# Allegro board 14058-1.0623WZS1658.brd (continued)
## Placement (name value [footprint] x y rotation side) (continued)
PR4413  4K32R2F-GP  [R402H16]  50.49 252.59 90 bottom
PR4414  31K6R2F-GP  [R402H16]  52.27 254.37 270 top
PR4415  51R2F-2-GP  [R402H16]  50.49 253.86 90 bottom
PR4416  4K99R2F-L-GP  [R402H16]  40.46 238.62 0 top
PR4417  5K9R2F-GP  [R402H16]  39.95 237.1 270 top
PR4418  24K9R2F-L-GP  [R402H16]  45.03 251.19 90 top
PR4419  4K99R2F-L-GP  [R402H16]  48.08 254.24 0 bottom
PR4420  5K9R2F-GP  [R402H16]  50.36 255.51 270 bottom
PR4421  10R2J-2-GP  [R402H14]  50.87 241.67 270 bottom
PR4422  10R2J-2-GP  [R402H14]  50.87 239.25 90 bottom
PR4423  80K6R2F-GP  [R402H16]  52.39 243.45 180 bottom
PR4424  22K1R2F-L-GP  [R402H16]  48.96 244.72 270 bottom
PR4425  174KR2F-GP  [R402H16]  52.65 244.46 270 top
PR4426  100KR2F-L1-GP  [R402H16]  54.3 245.22 0 top
PR4427  4K02R2F-GP  [R402H16]  50.87 243.06 90 bottom
PR4428  100KR2F-L1-GP  [R402H16]  49.22 241.67 0 bottom
PR4429  4K02R2F-GP  [R402H16]  50.87 240.52 90 bottom
PR4430  100KR2F-L1-GP  [R402H16]  49.22 239.64 0 bottom
PR4431  10R2J-2-GP  [R402H14]  29.15 242.05 0 top
PR4432  10R2J-2-GP  [R402H14]  31.82 240.91 180 top
PR4433  10R2J-2-GP  [R402H14]  38.55 239.13 180 top
PR4434  80K6R2F-GP  [R402H16]  53.16 242.3 0 top
PR4435  120KR2F-L-GP  [R402H16]  29.41 243.57 90 top
PR4436  120KR2F-L-GP  [R402H16]  34.87 239.25 270 top
PR4437  120KR2F-L-GP  [R402H16]  36.52 239.13 0 top
PR4438  21KR2F-GP  [R402H16]  34.99 245.99 0 bottom
PR4439  100KR2F-L1-GP  [R402H16]  32.2 247.64 0 top
PR4440  180KR2F-GP  [R402H16]  32.58 245.99 90 top
PR4441  4K02R2F-GP  [R402H16]  32.58 243.7 90 top
PR4442  4K02R2F-GP  [R402H16]  34.11 240.91 180 top
PR4443  4K02R2F-GP  [R402H16]  36.39 237.6 90 top
PR4444  100KR2F-L1-GP  [R402H16]  34.23 242.94 180 top
PR4445  100KR2F-L1-GP  [R402H16]  32.96 240.91 180 top
PR4446  100KR2F-L1-GP  [R402H16]  38.04 238.75 90 bottom
PR4447  100R2F-L1-GP-U  [R402H14]  39.06 253.48 90 top
PR4448  45D3R2F-L-GP  [R402H16]  39.06 251.19 90 top
PR4449  75R2F-2-GP  [R402H16]  39.06 252.34 90 top
PR4450  1KR2F-3-GP  [R402H16]  35.5 249.8 0 bottom
PR4451  47R2F-GP  [R402H16]  33.85 250.43 270 bottom
PR4452  4K02R2F-GP  [R402H16]  31.31 248.91 0 bottom
PR4453  560KR2F-GP  [R402H16]  34.36 248.91 0 bottom
PR4454  4K02R2F-GP  [R402H16]  52.65 247.76 90 bottom
PR4455  1KR2F-3-GP  [R402H16]  49.98 246.87 0 bottom
PR4456  560KR2F-GP  [R402H16]  48.84 246.87 0 bottom
PR4457  47R2F-GP  [R402H16]  50.11 249.03 180 bottom
PR4458  10KR2F-2-GP  [R402H16]  45.03 250.05 90 top
PR4459  10R2F-L-GP  [R402H14]  38.8 253.1 0 bottom
PR4460  49D9R2F-GP  [R402H16]  41.09 253.1 0 bottom
PR4461  10KR2F-2-GP  [R402H16]  46.68 238.87 270 bottom
PR4462  36K5R2F-GP  [R402H16]  44.27 238.11 180 bottom
PR4464  NTC-100K-12-GP-U  [NTC-402H22-U]  63.06 251.65 0 bottom
PR4465  NTC-100K-12-GP-U  [NTC-402H22-U]  75.89 241.41 90 top
PR4466  NTC-100K-12-GP-U  [NTC-402H22-U]  31.95 188.33 270 top
PR4467  0R0402-PAD-2-GP  [0R0402-PAD-1]  39.95 253.1 180 bottom
PR4468  0R2J-2-GP  [R402H16]  32.58 242.56 270 top
PR4473  15KR2F-GP  [R402H16]  46.68 237.73 270 bottom
PR4474  52K3R2F-L-GP  [R402H16]  41.6 238.49 0 top
PR4475  10KR2J-3-GP  [R402H16]  149.68 122.8 90 top
PR4476  2D2R5J-1-GP  [R805H24]  45.41 255.38 90 bottom
PR4477  2KR2F-3-GP  [R402H16]  32.58 244.84 90 top
PR4801  100R2F-L1-GP-U  [R402H14]  24.33 163.05 180 top
PR4802  0R0402-PAD-2-GP  [0R0402-PAD-1]  24.45 164.96 0 top
PR4803  0R0402-PAD-2-GP  [0R0402-PAD-1]  23.31 164.96 0 top
PR5268  0R0402-PAD-2-GP  [0R0402-PAD-1]  71.11 34.01 270 top
PR5270  316KR3F-2-GP  [R603H22]  71.7 35.55 0 bottom
PR5274  -  [0R0402-PAD]  70.43 35.29 0 bottom
PR5276  D01R3721F-GP-U  [R3720H40]  82.56 43.5 180 top
PR5277  0R0402-PAD-2-GP  [0R0402-PAD-1]  72.72 33.25 180 top
PR5279  100KR2J-1-GP  [R402H16]  72.74 42.43 0 top
PR5281  1D5R2F-GP  [R402H16]  78.43 36.31 90 top
PR5284  20R5F-1GP  [R805H24]  77.29 33.77 0 bottom
PR5285  0R0402-PAD-2-GP  [0R0402-PAD-1]  73.76 33.25 180 top
PR5286  49K9R2F-L-GP  [R402H16]  71.44 38.72 90 bottom
PR5288  3D3MR2J-GP  [R402H16]  74.24 42.91 270 top
PR5290  -  [0R0402-PAD]  69.41 42.66 0 bottom
PR5291  100KR2J-1-GP  [R402H16]  72.33 45.45 180 top
PR5301  -  [0R0805-PAD]  6.8 133.72 90 bottom
PR5302  10KR2F-2-GP  [R402H16]  17.34 110.73 90 bottom
PR5303  10KR2F-2-GP  [R402H16]  7.82 119.75 90 bottom
PR5304  -  [0R0805-PAD]  9.9 107.63 270 top
PR5305  10KR2F-2-GP  [R402H16]  7.82 117.46 90 bottom
PR5306  88K7R2F-GP  [R402H16]  7.94 114.41 270 bottom
PR5307  2D2R5J-1-GP  [R805H24]  16.71 128.26 0 bottom
PR5308  2D2R5J-1-GP  [R805H24]  15.94 114.92 180 bottom
PR5309  10KR2F-2-GP  [R402H16]  7.94 113.4 90 bottom
PR5467  102KR2F-GP  [R402H16]  69.92 40.75 180 bottom
PR5468  53K6R2F-GP  [R402H16]  67.76 40.25 270 top
PR5469  45K3R2F-L-GP  [R402H16]  68.15 41.74 0 top
PR5470  120KR2F-L-GP  [R402H16]  67.06 41.78 180 top
PR5471  -  [0R0805-PAD]  6.8 232.27 90 top
PR5472  -  [0R0805-PAD]  6.8 230.24 90 top
PR5473  -  [0R0805-PAD]  6.8 228.21 90 top
PR5474  -  [0R0805-PAD]  6.8 215 90 top
PR5475  -  [0R0805-PAD]  6.8 217.03 90 top
PR5476  -  [0R0805-PAD]  6.8 212.97 90 top
PR5477  -  [0R0805-PAD]  121.61 257.92 90 top
PR5478  -  [0R0805-PAD]  121.61 261.99 90 top
PR5479  -  [0R0805-PAD]  121.61 264.02 90 top
PR5480  -  [0R0805-PAD]  121.61 259.96 90 top
PR5481  -  [0R0805-PAD]  157.83 110.73 180 top
PR5482  -  [0R0805-PAD]  159.76 110.73 180 top
PR5518  10KR2F-2-GP  [R402H16]  15.18 110.1 180 bottom
PR5519  -  [0R0805-PAD]  21.91 81.9 90 top
PR5520  -  [0R0805-PAD]  21.91 83.93 90 top
PR5521  -  [0R0805-PAD]  26.49 67.75 90 top
PR5522  10KR2J-3-GP  [R402H16]  95.27 102.35 0 top
PR5523  10KR2J-3-GP  [R402H16]  77.03 77.08 90 top
PR5525  10KR2J-3-GP  [R402H16]  38.8 106.67 90 top
PR8302  2D2R5J-1-GP  [R805H24]  104.64 107.3 180 top
PR8303  20KR2F-L-GP  [R402H16]  99.61 108.83 270 top
PR8304  100KR2F-L1-GP  [R402H16]  104.46 97.65 270 top
PR8305  2KR2F-3-GP  [R402H16]  97.73 105.27 0 top
PR8306  0R0402-PAD-2-GP  [0R0402-PAD-1]  97.96 100.32 270 bottom
PR8308  33KR2F-GP  [R402H16]  100.5 108.65 180 bottom
PR8309  20KR2F-L-GP  [R402H16]  97.73 105.27 0 bottom
PR8311  10KR2F-2-GP  [R402H16]  97 103.69 270 top
PR8312  35K7R2F-GP  [R402H16]  106.7 99.91 0 top
PR8313  2D2R5J-1-GP  [R805H24]  105.61 96.13 0 bottom
PR8315  -  [0R0402-PAD]  105.35 96.13 180 top
PR8316  18KR2F-GP  [R402H16]  96.59 105.85 180 top
PR8317  0R0402-PAD-2-GP  [0R0402-PAD-1]  96.84 102.98 0 bottom
PR8318  51R2F-2-GP  [R402H16]  98.62 102.86 0 top
PR8319  -  [0R0402-PAD]  103.83 95.62 270 top
PR8320  0R2J-2-GP  [R402H16]  96.59 107.99 180 top
PR8323  5K9R3F-3-GP  [R603H22]  101.42 96 0 top
PR8324  0R0402-PAD-2-GP  [0R0402-PAD-1]  100.3 106.21 180 top
PR8325  -  [0R0402-PAD]  103.88 109.76 90 top
PR8326  82KR2F-1-GP  [R402H16]  96.34 101.28 0 top
PR8327  100KR2F-L1-GP  [R402H16]  103.83 96.63 90 top
PR8328  47KR2J-2-GP  [R402H16]  102.63 108.27 90 top
PR8329  100R2F-L1-GP-U  [R402H14]  95.7 102.98 180 bottom
PR8330  2D2R5J-1-GP  [R805H24]  101.67 95.16 0 bottom
PR8331  10KR2J-3-GP  [R402H16]  114.5 101.08 0 bottom
PR8333  100R2F-L1-GP-U  [R402H14]  96.21 100.95 180 bottom
PR8334  47KR2F-GP  [R402H16]  100.65 100.95 180 bottom
PR8335  1KR2J-1-GP  [R402H16]  100.4 106.29 90 bottom
PR8338  0R0402-PAD-2-GP  [0R0402-PAD-1]  39.19 105.07 0 top
PR8339  0R2J-2-GP  [R402H16]  38.07 105.07 0 top
PR8609  -  [0R0402-PAD]  46.93 86.6 90 top
PR8610  -  [0R0402-PAD]  39.69 111.49 90 top
PR8611  -  [0R0402-PAD]  39.69 110.35 90 top
PR8612  -  [0R0402-PAD]  46.93 88.63 90 top
PR8613  -  [0R0402-PAD]  46.93 89.65 90 top
PR8614  -  [0R0402-PAD]  46.93 90.66 90 top
PR8615  2D2R5J-1-GP  [R805H24]  38.07 97.65 180 top
PR8616  2D2R2F-GP  [R402H16]  43.5 110.6 0 bottom
PR8617  100KR2F-L1-GP  [R402H16]  37.25 101.28 90 top
PR8618  0R3J-0-U-GP  [R603H22]  45.03 109.46 180 top
PR8619  -  [0R0402-PAD]  46.93 85.46 90 top
PR8620  6K98R2F-GP  [R402H16]  38.68 103.49 90 top
PR8621  10KR2F-2-GP  [R402H16]  40.2 103.16 180 top
PR8622  -  [0R0402-PAD]  46.93 87.62 90 top
PR8623  10KR2J-3-GP  [R402H16]  37.53 107.68 90 top
PR8624  NTC-100K-12-GP-U  [NTC-402H22-U]  17.54 235.01 180 bottom
PR8625  3K3R2J-3-GP  [R402H16]  68.14 38.09 90 top
PR8626  3K3R2J-3-GP  [R402H16]  68.14 39.1 90 top
PSWD1  JOWLE-CON2-5-GP  [A2541WV0-1EX2PA-6T]  144.6 124.06 270 top
PT1  SE47U25VM-13-GP  [SE361414H241]  12.52 199.5 180 top
PT2  E820U2D5VM-6-GP  [ECAP-100D6D3H375]  43.12 219.19 270 top
PT3  E820U2D5VM-6-GP  [ECAP-100D6D3H375]  43 187.69 270 top
PT4  E820U2D5VM-6-GP  [ECAP-100D6D3H375]  43 195.57 270 top
PT5  E820U2D5VM-6-GP  [ECAP-100D6D3H375]  43 203.44 270 top
PT6  E820U2D5VM-6-GP  [ECAP-100D6D3H375]  43.12 211.31 270 top
PT7  SE47U25VM-13-GP  [SE361414H241]  12.52 218.3 180 top
PT8  SE47U25VM-13-GP  [SE361414H241]  12.52 227.7 0 top
PT9  SE47U25VM-13-GP  [SE361414H241]  84.14 256.83 90 top
PT11  E820U2D5VM-6-GP  [ECAP-100D6D3H375]  77.79 237.1 270 top
PT12  E820U2D5VM-6-GP  [ECAP-100D6D3H375]  81.6 230.11 270 top
PT13  E820U2D5VM-6-GP  [ECAP-100D6D3H375]  85.67 237.1 270 top
PT14  E820U2D5VM-6-GP  [ECAP-100D6D3H375]  89.48 230.11 270 top
PT15  SE47U25VM-13-GP  [SE361414H241]  115.64 256.65 0 top
PT16  SE47U25VM-13-GP  [SE361414H241]  27.76 148.45 90 top
PT17  E820U2D5VM-6-GP  [ECAP-100D6D3H375]  43.63 170.67 270 top
PT18  E820U2D5VM-6-GP  [ECAP-100D6D3H375]  43.63 162.8 270 top
PT20  E820U2D5VM-6-GP  [ECAP-100D6D3H375]  39.31 180.58 180 top
PT22  SE47U25VM-13-GP  [SE361414H241]  32.58 68.82 180 top
PT23  SE220U6D3VM-18-GP  [SE341619H241]  54.55 79.74 180 top
PT24  SE220U6D3VM-18-GP  [SE341619H241]  65.35 67.55 180 top
PT25  SE47U25VM-13-GP  [SE361414H241]  160.09 217.41 0 top
PT26  E820U2D5VM-6-GP  [ECAP-100D6D3H375]  128.09 220.46 270 top
PT27  E820U2D5VM-6-GP  [ECAP-100D6D3H375]  128.09 212.58 270 top
PT28  SE47U25VM-13-GP  [SE361414H241]  156.15 116.45 270 top
PT29  E820U2D5VM-6-GP  [ECAP-100D6D3H375]  158.13 103.2 180 top
PT30  E820U2D5VM-6-GP  [ECAP-100D6D3H375]  167.84 97.75 180 top
PT32  E820U2D5VM-6-GP  [ECAP-100D6D3H375]  109.04 119.75 270 top
PT34  E820U2D5VM-6-GP  [ECAP-100D6D3H375]  108.91 111.62 270 top
PT35  SE47U25VM-13-GP  [SE361414H241]  112.46 85.08 90 top
PU1  AON6520-GP  [PPAK-8P-5262H40]  110.56 97.4 180 top
PU2  AON6520-GP  [PPAK-8P-5262H40]  19.63 198.36 90 top
PU3  AON6520-GP  [PPAK-8P-5262H40]  19.63 198.36 270 bottom
PU4  NCP81151MNTBG-GP  [DFN8G2-G1309-UH40]  10.61 189.34 90 top
PU5  AON6510-GP  [PPAK-8P-5262H40]  21.41 189.47 270 top
PU6  AON6510-GP  [PPAK-8P-5262H40]  21.41 189.47 90 bottom
PU7  AON6520-GP  [PPAK-8P-5262H40]  19.63 214.87 90 top
PU8  AON6520-GP  [PPAK-8P-5262H40]  19.63 214.87 270 bottom
PU9  NCP81151MNTBG-GP  [DFN8G2-G1309-UH40]  10.61 208.14 90 top
PU10  AON6510-GP  [PPAK-8P-5262H40]  21.41 205.98 270 top
PU11  AON6510-GP  [PPAK-8P-5262H40]  21.41 205.98 90 bottom
PU12  AON6520-GP  [PPAK-8P-5262H40]  19.63 230.62 90 top
PU13  AON6520-GP  [PPAK-8P-5262H40]  19.63 230.62 270 bottom
PU14  NCP81151MNTBG-GP  [DFN8G2-G1309-UH40]  13.4 235.32 0 top
PU15  AON6510-GP  [PPAK-8P-5262H40]  21.41 221.73 270 top
PU16  AON6510-GP  [PPAK-8P-5262H40]  21.41 221.73 90 bottom
PU17  AON6520-GP  [PPAK-8P-5262H40]  76.14 258.05 180 bottom
PU18  AON6520-GP  [PPAK-8P-5262H40]  76.14 258.05 0 top
PU19  NCP81151MNTBG-GP  [DFN8G2-G1309-UH40]  67.25 261.1 0 top
PU20  AON6510-GP  [PPAK-8P-5262H40]  67 251.32 0 bottom
PU21  AON6510-GP  [PPAK-8P-5262H40]  67 251.32 180 top
PU22  AON6520-GP  [PPAK-8P-5262H40]  108.27 259.7 180 bottom
PU23  AON6520-GP  [PPAK-8P-5262H40]  108.27 259.7 0 top
PU24  NCP81151MNTBG-GP  [DFN8G2-G1309-UH40]  92.91 260.34 180 top
PU25  AON6510-GP  [PPAK-8P-5262H40]  99.26 258.05 0 bottom
PU26  AON6510-GP  [PPAK-8P-5262H40]  99.26 258.05 180 top
PU27  AON6520-GP  [PPAK-8P-5262H40]  25.72 155.43 180 top
PU28  NCP5230MNTWG-GP-U  [QFN16G3-G1D85-UH40]  25.72 136.64 0 top
PU29  AON6510-GP  [PPAK-8P-5262H40]  32.33 157.21 180 bottom
PU30  AON6510-GP  [PPAK-8P-5262H40]  32.33 157.21 0 top
PU31  AON7410-GP  [PPAK-8P-3232H36]  23.06 180.07 90 top
PU32  RT8237CZQW-2-GP  [DFN10G3-G265175H32]  20.64 168.01 180 top
PU33  AON7506-GP  [PPAK-8P-3232H36]  24.58 175.63 270 top
PU34  AON7410-GP  [PPAK-8P-3232H36]  38.35 81.77 90 top
PU35  RT8243AZQW-GP  [QFN20-G1D75H32]  29.28 75.68 270 bottom
PU36  AON6520-GP  [PPAK-8P-5262H40]  42.74 65.01 90 top
PU37  AON7506-GP  [PPAK-8P-3232H36]  39.87 77.33 270 top
PU38  AON6510-GP  [PPAK-8P-5262H40]  44.52 71.61 270 top
PU39  AON6520-GP  [PPAK-8P-5262H40]  150.69 218.81 270 top
PU40  RT8207PGQW-GP  [QFN20-G1D75H32]  168.63 215.62 90 bottom
PU41  AON6510-GP  [PPAK-8P-5262H40]  148.91 212.2 270 bottom
PU42  AON6510-GP  [PPAK-8P-5262H40]  148.91 212.2 90 top
PU43  AON6520-GP  [PPAK-8P-5262H40]  164.15 120.64 0 top
PU44  RT8237CZQW-2-GP  [DFN10G3-G265175H32]  154.63 124.45 270 bottom
PU45  AON6510-GP  [PPAK-8P-5262H40]  170.76 118.86 180 top
PU46  AON6510-GP  [PPAK-8P-5262H40]  170.76 118.86 0 bottom
PU4401  NCP81203MNTXG-SI2-GP  [LFQFN52J6-G4D8H40]  42.11 245.48 180 bottom
PU5202  AON6510-GP  [PPAK-8P-5262H40]  119.2 99.05 0 top
PU5203  AON6520-GP  [PPAK-8P-5262H40]  110.56 97.4 0 bottom
PU5204  AON6510-GP  [PPAK-8P-5262H40]  119.2 99.05 180 bottom
PU5301  RT8289GSP-GP  [SOIC8-G2D3H70]  11.88 116.95 180 bottom
PU5302  APL5930KAI-TRG-1-GP  [SOIC8-G3530H63]  105.73 129.65 270 top
PU8602  APW8713QBI-GP  [QFN23G4-G2PH34]  44.01 104.13 90 top
PWRCN1  ACES-CON10-30-GP  [51530-01041-W01]  33.75 18.17 270 top
Q1  DMN5L06K-7-GP  [SOT23DGS2D4H48]  150.31 95.49 0 bottom
Q2  MMBT3904-5-GP  [SOT23CBE2D4H46]  151.38 101.48 180 top
Q3  2N7002H-GP  [SOT23DGS2D4H44]  154.12 95.49 180 bottom
Q4  DMN5L06K-7-GP  [SOT23DGS2D4H48]  150.31 95.49 180 top
Q5  MMBT3906-4-GP  [SOT23CBE2D4H44]  163.47 55.74 270 top
Q6  2N7002EDW-2-GP  [SOT-363H44]  122.85 59.64 180 bottom
Q7  2N7002A-7-GP  [SOT23DGS2D4H48]  185.36 57.52 0 top
Q8  2N7002H-GP  [SOT23DGS2D4H44]  110.86 58.03 0 bottom
Q10  2N7002KDW-GP  [SOT-363H44]  94.94 60.31 180 top
Q12  2N7002A-7-GP  [SOT23DGS2D4H48]  184.22 32.37 180 top
Q13  MMBT3904DW-GP  [SOT-363H44]  184.35 39.53 180 top
Q14  2N7002-11-GP  [SOT23DGS2D4H44]  181.93 72.38 270 top
Q15  AZ5125-02S-R7G-GP  [SOT23-2D4-312H46]  185.11 80.38 0 top
Q16  AZ5125-02S-R7G-GP  [SOT23-2D4-312H46]  182.06 76.19 90 top
Q17  AZ5125-02S-R7G-GP  [SOT23-2D4-312H46]  105.1 36.82 270 top
Q18  MMBT3904-4-GP  [SOT23CBE2D4H44]  178.25 73.9 0 top
Q23  MMBT3904DW-GP  [SOT-363H44]  52.14 43.29 180 top
Q24  2N7002A-7-GP  [SOT23DGS2D4H48]  51.76 28.31 90 bottom
Q26  MMBT3904-4-GP  [SOT23CBE2D4H44]  51.76 28.31 270 top
Q29  AO4468L-GP  [SOIC8H69]  81.86 57.77 270 bottom
Q30  2N7002A-7-GP  [SOT23DGS2D4H48]  79.14 56.07 0 top
Q31  2N7002A-7-GP  [SOT23DGS2D4H48]  77.64 62.47 270 top
Q53  2N7002A-7-GP  [SOT23DGS2D4H48]  96.51 112.76 90 top
Q54  AO3413L-GP  [SOT23DGS2D8H50]  96.59 119.87 0 top
Q56  AO3413L-GP  [SOT23DGS2D8H50]  141.8 227.82 0 bottom
Q57  2N7002K-2-GP  [SOT23DGS2D4H44]  125.57 254.08 270 top
Q58  2N7002A-7-GP  [SOT23DGS2D4H48]  147.95 236.44 270 bottom
Q59  MMBT3906-4-GP  [SOT23CBE2D4H44]  94.18 88.38 90 top
Q60  MMBT3904-4-GP  [SOT23CBE2D4H44]  147.95 240.05 270 bottom
Q61  MMBT3904-4-GP  [SOT23CBE2D4H44]  46.04 6.84 90 top
Q62  MMBT3904-4-GP  [SOT23CBE2D4H44]  49.73 6.92 180 top
Q63  MMBT3904-4-GP  [SOT23CBE2D4H44]  47.06 10.65 90 top
Q64  2N7002A-7-GP  [SOT23DGS2D4H48]  36.85 7.4 0 top
Q65  2N7002A-7-GP  [SOT23DGS2D4H48]  42.23 12.18 90 top
Q76  MMBT3904-4-GP  [SOT23CBE2D4H44]  170 206.62 270 bottom
Q103  2N7002A-7-GP  [SOT23DGS2D4H48]  28.62 54.19 270 top
Q1227  2N7002H-GP  [SOT23DGS2D4H44]  8.6 162.62 90 top
Q1228  2N7002KDW-GP  [SOT-363H44]  110.43 240.91 180 top
Q1233  2N7002EDW-2-GP  [SOT-363H44]  37.79 154.16 180 top
Q1234  AO3404AL-GP  [SOT23DGS2D8H50]  34.87 147.43 180 top
Q1249  2N7002A-7-GP  [SOT23DGS2D4H48]  169.87 52.95 0 bottom
Q1259  AO4286-GP  [SOIC8H69]  14.8 7.99 90 bottom
Q1260  MMBT3904-4-GP  [SOT23CBE2D4H44]  6.04 17.26 90 bottom
Q1261  2N7002A-7-GP  [SOT23DGS2D4H48]  18.74 38.85 90 bottom
Q1262  2N7002A-7-GP  [SOT23DGS2D4H48]  18.36 34.28 90 bottom
Q1263  MMBT3904-4-GP  [SOT23CBE2D4H44]  16.07 30.59 270 bottom
Q1264  AO3413L-GP  [SOT23DGS2D8H50]  51.89 24.24 0 top
Q1265  MMBT3904-4-GP  [SOT23CBE2D4H44]  55.95 19.42 0 bottom
Q1266  MMBT3904-4-GP  [SOT23CBE2D4H44]  55.97 19.47 180 top
Q1267  MMBT3904-4-GP  [SOT23CBE2D4H44]  57.35 14.34 90 top
Q6701  2N7002KDW-GP  [SOT-363H44]  26.49 110.35 0 top
Q6704  MMBT3904-4-GP  [SOT23CBE2D4H44]  109.8 83.43 270 bottom
Q7903  2N7002-7F-GP  [SOT23DGS2D4H44]  111.55 44.11 90 top
Q9501  2N7002KDW-GP  [SOT-363H44]  51 20.69 90 top
Q9502  2N7002KDW-GP  [SOT-363H44]  51 17.64 270 top
Q9503  2N7002KDW-GP  [SOT-363H44]  57.6 14.21 180 bottom
Q9601  AO3418L-GP  [SOT23DGS2D8H50]  38.04 39.99 180 bottom
Q9602  LMBT3906LT1G-1-GP  [SOT23CBE2D4H44]  43.76 40.75 270 bottom
Q9614  2N7002KDW-GP  [SOT-363H44]  28.01 27.8 0 bottom
Q9619  AO3418L-GP  [SOT23DGS2D8H50]  33.6 27.8 90 bottom
Q9620  2N7002KDW-GP  [SOT-363H44]  181.3 28.82 270 top
Q9624  AO3418L-GP  [SOT23DGS2D8H50]  16.71 173.6 270 top
Q9626  2N7002A-7-GP  [SOT23DGS2D4H48]  180.54 32.37 0 top
Q9628  MMBT3904DW-GP  [SOT-363H44]  19.12 44.18 180 bottom
Q9629  MMBT3904DW-GP  [SOT-363H44]  26.23 48.63 270 bottom
Q9630  2N7002K-2-GP  [SOT23DGS2D4H44]  105.73 90.79 180 top
Q9631  MMBT3904-4-GP  [SOT23CBE2D4H44]  94.18 88.38 270 bottom
Q9632  2N7002EDW-2-GP  [SOT-363H44]  90.21 130.31 90 top
Q9633  2N7002EDW-2-GP  [SOT-363H44]  96.34 130.54 90 top
Q9634  MMBT3904-4-GP  [SOT23CBE2D4H44]  82.24 48.25 90 bottom
Q9635  MMBT3904-4-GP  [SOT23CBE2D4H44]  93.16 57.52 90 bottom
Q9646  2N7002KDW-GP  [SOT-363H44]  41.47 8.24 180 top
Q9648  AO3413L-GP  [SOT23DGS2D8H50]  28.26 56.37 90 bottom
Q9650  2N7002A-7-GP  [SOT23DGS2D4H48]  32.07 54.6 180 bottom
R1  -  [0R0402-PAD]  102.05 192.9 270 bottom
R2  -  [0R0402-PAD]  102.05 194.04 270 bottom
R3  2R2F-GP  [R402H16]  109.42 224.9 270 bottom
R4  2R2F-GP  [R402H16]  109.42 226.05 270 bottom
R5  24D9R2F-L-GP  [R402H16]  105.1 225.67 90 bottom
R6  -  [0R0402-PAD]  82.49 144.39 0 bottom
R7  -  [0R0402-PAD]  81.35 144.39 0 bottom
R8  51R2F-2-GP  [R402H16]  57.73 139.56 270 top
R9  -  [0R0402-PAD]  83.8 143.75 180 top
R10  1KR2J-1-GP  [R402H16]  52.14 134.73 180 top
R11  -  [0R0402-PAD]  82.66 143.75 180 top
R12  51R2F-2-GP  [R402H16]  37.38 231.25 270 top
R13  -  [0R0402-PAD]  84.78 145.15 0 bottom
R14  51R2F-2-GP  [R402H16]  36.65 143.88 90 top
R15  -  [0R0402-PAD]  83.64 145.15 0 bottom
R16  56D2R2F-GP  [R402H16]  37.25 234.68 270 top
R17  45D3R2F-L-GP  [R402H16]  41.34 234.68 270 top
R18  100R2F-L1-GP-U  [R402H14]  41.34 231.25 270 top
R19  1MR2J-1-GP  [R402H16]  21.28 39.23 0 bottom
R20  10KR2J-3-GP  [R402H16]  109.42 232.14 180 top
R22  -  [0R0402-PAD]  37.25 235.83 270 top
R23  220R2F-GP  [R402H16]  37.25 233.54 270 top
R24  10KR2J-3-GP  [R402H16]  107.51 229.6 90 bottom
R25  0R2J-2-GP  [R402H16]  41.34 233.54 90 top
R27  -  [0R0402-PAD]  41.34 235.83 270 top
R28  0R2J-2-GP  [R402H16]  41.34 230.11 90 top
R30  -  [0R0402-PAD]  41.34 232.4 270 top
R31  0R2J-2-GP  [R402H16]  109.26 237.22 270 top
R32  51R2F-2-GP  [R402H16]  42.49 121.27 270 top
R33  6K04R2F-GP  [R402H16]  60.64 139.11 180 top
R35  2K8R2F-GP  [R402H16]  61.65 139.11 180 top
R37  -  [0R0402-PAD]  58.86 144.83 180 top
R38  -  [0R0402-PAD]  38.8 140.96 90 top
R39  0R0402-PAD-2-GP  [0R0402-PAD-1]  39.43 144.07 0 top
R40  0R0402-PAD-2-GP  [0R0402-PAD-1]  38.41 144.07 0 top
R41  0R2J-2-GP  [R402H16]  59.87 144.83 0 top
R42  10KR2J-3-GP  [R402H16]  18.48 31.23 0 bottom
R43  0R0402-PAD-2-GP  [0R0402-PAD-1]  32.92 116.83 270 top
R44  0R0402-PAD-2-GP  [0R0402-PAD-1]  61.03 145.53 0 top
R45  49D9R2F-GP  [R402H16]  70.05 179.44 0 top
R46  1KR2J-1-GP  [R402H16]  41.47 133.34 270 top
R47  1KR2J-1-GP  [R402H16]  41.47 132.19 270 top
R48  1KR2J-1-GP  [R402H16]  41.47 131.05 270 top
R49  1KR2J-1-GP  [R402H16]  51.63 131.69 90 top
R50  1KR2J-1-GP  [R402H16]  41.73 128.89 270 top
R51  1KR2J-1-GP  [R402H16]  41.47 146.8 270 top
R52  1KR2J-1-GP  [R402H16]  42.11 127.24 0 top
R53  1KR2J-1-GP  [R402H16]  41.47 145.78 270 top
R54  1KR2J-1-GP  [R402H16]  41.6 137.65 270 top
R55  1KR2J-1-GP  [R402H16]  37.03 157.72 90 top
R56  1KR2J-1-GP  [R402H16]  37.46 133.34 180 top
R57  1KR2J-1-GP  [R402H16]  36.31 133.34 180 top
R58  1KR2J-1-GP  [R402H16]  41.6 139.56 270 top
R59  1KR2J-1-GP  [R402H16]  39.57 146.04 0 top
R60  1KR2J-1-GP  [R402H16]  37.53 128.64 90 top
R61  1KR2J-1-GP  [R402H16]  37.53 127.49 90 top
R62  1KR2J-1-GP  [R402H16]  44.77 152.77 270 top
R63  24D9R2F-L-GP  [R402H16]  71.6 179.69 270 top
R64  -  [0R0402-PAD]  79.7 179.95 90 top
R65  0R2J-2-GP  [R402H16]  79.7 178.47 270 top
R66  20R2J-3-GP  [R402H16]  139.87 61.3 0 top
R68  0R3J-L1-GP  [R603H22]  37.28 145.91 180 top
R71  24D9R2F-L-GP  [R402H16]  71.65 178.57 90 top
R72  20R2F-GP  [R402H16]  147 61.33 180 top
R73  10KR2J-3-GP  [R402H16]  168.73 136.77 270 bottom
R74  10KR2J-3-GP  [R402H16]  145.74 136 0 bottom
R75  10KR2J-3-GP  [R402H16]  148.79 136 0 bottom
R76  1KR2F-3-GP  [R402H16]  143.93 194.97 90 bottom
R77  -  [0R0402-PAD]  143.45 197.6 0 bottom
R78  1KR2F-3-GP  [R402H16]  143.88 196.07 270 bottom
R79  2R2F-GP  [R402H16]  144.85 199.25 90 bottom
R80  24D9R2F-L-GP  [R402H16]  144.34 200.77 180 bottom
R81  0R0402-PAD-2-GP  [0R0402-PAD-1]  154.37 188.84 90 bottom
R82  1KR2F-3-GP  [R402H16]  154.12 156.07 0 bottom
R83  -  [0R0402-PAD]  153.61 157.59 270 bottom
R84  1KR2F-3-GP  [R402H16]  153.1 156.07 180 bottom
R85  10KR2J-3-GP  [R402H16]  160.72 136.13 180 bottom
R86  10KR2J-3-GP  [R402H16]  160.72 138.16 0 bottom
R87  1KR2F-3-GP  [R402H16]  160.34 193.79 270 bottom
R88  -  [0R0402-PAD]  159.84 195.31 0 bottom
R89  1KR2F-3-GP  [R402H16]  160.85 195.31 0 bottom
R90  2R2F-GP  [R402H16]  159.84 199 180 bottom
R91  24D9R2F-L-GP  [R402H16]  162.38 199 270 bottom
R92  0R0402-PAD-2-GP  [0R0402-PAD-1]  168.85 189.09 270 bottom
R93  1KR2F-3-GP  [R402H16]  169.11 159.63 90 bottom
R94  -  [0R0402-PAD]  169.11 158.48 270 bottom
R95  1KR2F-3-GP  [R402H16]  168.22 156.83 180 bottom
R96  10KR2J-3-GP  [R402H16]  164.03 78.09 0 top
R99  1KR2J-1-GP  [R402H16]  136.47 81.39 180 bottom
R100  1KR2J-1-GP  [R402H16]  134.88 94.33 180 top
R103  10KR2J-3-GP  [R402H16]  162.12 79.36 90 top
R104  499R2F-2-GP  [R402H16]  150.18 90.66 90 bottom
R105  499R2F-2-GP  [R402H16]  155.26 92.82 90 bottom
R106  33R2J-2-GP  [R402H16]  145.95 61.31 180 top
R107  33R2J-2-GP  [R402H16]  153.1 67.3 0 bottom
R108  33R2J-2-GP  [R402H16]  155.69 69.73 90 bottom
R109  33R2J-2-GP  [R402H16]  151.96 67.3 0 bottom
R111  33R2J-2-GP  [R402H16]  154.25 67.3 0 bottom
R113  33R2J-2-GP  [R402H16]  144.9 61.3 180 top
R115  -  [0R0402-PAD]  162.63 74.33 90 top
R116  10KR2J-3-GP  [R402H16]  165.17 73.77 180 top
R117  8K2R2J-3-GP  [R402H16]  153.66 102.25 180 top
R118  8K2R2J-3-GP  [R402H16]  148.15 100.19 90 top
R119  4K7R2J-2-GP  [R402H16]  165.93 72.12 90 top
R120  3KR2J-2-GP  [R402H16]  159.58 56.88 0 top
R122  10KR2J-3-GP  [R402H16]  138.63 67.17 0 bottom
R123  10KR2J-3-GP  [R402H16]  166.82 73.65 270 top
R124  1KR2J-1-GP  [R402H16]  151.83 98.03 90 bottom
R126  0R2J-2-GP  [R402H16]  156.03 78.22 0 bottom
R127  1KR2J-1-GP  [R402H16]  160.09 77.96 180 bottom
R128  2K2R2J-2-GP  [R402H16]  151.82 58.6 180 top
R131  0R0402-PAD-2-GP  [0R0402-PAD-1]  146.74 58.41 0 top
R132  51R2F-2-GP  [R402H16]  145.69 58.41 0 top
R133  1KR2J-1-GP  [R402H16]  151.83 98.03 270 top
R134  10KR2J-3-GP  [R402H16]  8.07 19.87 270 bottom
R135  4K7R2J-2-GP  [R402H16]  10.23 20.05 90 top
R137  1K5R2J-3-GP  [R402H16]  172.41 77.58 270 bottom
R138  20KR2F-L-GP  [R402H16]  147.26 121.4 180 top
R139  0R2J-2-GP  [R402H16]  158.57 56.88 180 top
R140  0R2J-2-GP  [R402H16]  152.09 121.27 0 top
R141  4K7R2J-2-GP  [R402H16]  147.26 125.46 0 top
R142  -  [0R0402-PAD]  157.42 57.39 0 top
R143  1KR2J-1-GP  [R402H16]  5.63 19.44 90 top
R145  33R2J-2-GP  [R402H16]  172.41 78.73 270 bottom
R146  20KR2F-L-GP  [R402H16]  148.91 120.89 180 top
R147  4K7R2J-2-GP  [R402H16]  150.95 120.89 0 top
R150  0R0402-PAD-2-GP  [0R0402-PAD-1]  134.69 123.3 180 top
R151  10KR2J-3-GP  [R402H16]  132.78 122.54 180 top
R152  4K7R2J-2-GP  [R402H16]  38.42 146.04 0 top
R153  1KR2J-1-GP  [R402H16]  162.65 58.15 270 top
R154  1KR2J-1-GP  [R402H16]  152.27 60.06 270 top
R155  -  [0R0402-PAD]  152.96 58.6 180 top
R156  10KR2J-3-GP  [R402H16]  157.64 77.37 90 top
R157  10KR2J-3-GP  [R402H16]  163.77 84.57 90 top
R158  10KR2J-3-GP  [R402H16]  144.28 91.88 90 bottom
R159  2K7R2F-GP  [R402H16]  133.42 63.23 180 top
R160  10KR2J-3-GP  [R402H16]  164.03 83.04 90 top
R161  10KR2J-3-GP  [R402H16]  164.15 80.76 90 top
R162  10KR2J-3-GP  [R402H16]  161.87 81.39 180 top
R163  -  [0R0402-PAD]  158.67 78.42 270 top
R164  -  [0R0402-PAD]  163.77 85.84 270 top
R165  10KR2J-3-GP  [R402H16]  157.55 86.47 270 bottom
R166  -  [0R0402-PAD]  144.18 93 270 bottom
R168  10KR2J-3-GP  [R402H16]  144.18 97.32 90 bottom
R169  10KR2J-3-GP  [R402H16]  160.22 84.66 270 top
R170  10KR2J-3-GP  [R402H16]  160.22 85.8 270 top
R172  10KR2J-3-GP  [R402H16]  157.55 87.62 270 bottom
R173  10KR2J-3-GP  [R402H16]  160.22 86.94 270 top
R174  10KR2J-3-GP  [R402H16]  157.55 88.76 270 bottom
R175  10KR2J-3-GP  [R402H16]  157.55 89.9 270 bottom
R176  10KR2J-3-GP  [R402H16]  157.49 85.14 90 top
R177  10KR2J-3-GP  [R402H16]  157.49 86.18 90 top
R178  1MR2J-1-GP  [R402H16]  124.1 69.15 0 top
R179  0R0402-PAD-2-GP  [0R0402-PAD-1]  161.87 69.96 270 top
R180  10MR3F-GP  [R603H22]  164.53 69.84 180 top
R181  100R2F-L1-GP-U  [R402H14]  125.67 74.31 0 top
R188  113R2F-GP  [R402H16]  143.83 67.04 180 bottom
R189  1KR2J-1-GP  [R402H16]  143.2 65.14 180 bottom
R190  1KR2J-1-GP  [R402H16]  144 71.87 90 bottom
R191  -  [0R0402-PAD]  143.02 94.5 180 top
R192  10KR2J-3-GP  [R402H16]  87.83 121.37 270 bottom
R193  200R2F-L-GP  [R402H16]  75.13 125.08 90 top
R194  80D6R2F-L-GP  [R402H16]  60.65 111.62 90 top
R195  162R2F-GP  [R402H16]  58.74 110.48 270 top
R196  10KR2J-3-GP  [R402H16]  157.68 74.79 90 bottom
R197  10KR2J-3-GP  [R402H16]  157.17 73.65 90 bottom
R198  33R2J-2-GP  [R402H16]  162.5 76.57 90 top
R199  10KR2J-3-GP  [R402H16]  130.5 101.21 90 top
R200  -  [0R0402-PAD]  159.2 73.65 270 bottom
R203  10KR2J-3-GP  [R402H16]  164.79 79.62 90 top
R205  4K7R2J-2-GP  [R402H16]  157.55 89.9 90 top
R217  4K7R2J-2-GP  [R402H16]  161.49 82.92 270 top
R218  4K7R2J-2-GP  [R402H16]  157.05 82.93 180 top
R219  10KR2F-2-GP  [R402H16]  99.13 98.03 90 top
R221  4K7R2J-2-GP  [R402H16]  148.28 92.06 180 bottom
R222  4K7R2J-2-GP  [R402H16]  147.52 94.22 90 bottom
R223  20KR2J-L2-GP  [R402H16]  147.52 95.36 270 bottom
R224  20KR2J-L2-GP  [R402H16]  148.28 90.54 90 bottom
R226  1KR2J-1-GP  [R402H16]  167.2 61.2 0 top
R227  20KR2J-L2-GP  [R402H16]  151.07 92.32 0 bottom
R228  20KR2J-L2-GP  [R402H16]  166.06 61.2 180 top
R229  2K2R2J-2-GP  [R402H16]  159.84 58.41 90 top
R231  10KR2F-2-GP  [R402H16]  99.13 96 90 top
R234  49K9R2F-L-GP  [R402H16]  99.13 96 90 bottom
R235  243R2F-2-GP  [R402H16]  91.28 81.82 90 top
R236  20KR2J-L2-GP  [R402H16]  157.68 80.76 270 bottom
R237  10KR2F-2-GP  [R402H16]  99.13 97.01 90 bottom
R238  10KR2F-2-GP  [R402H16]  99.13 97.01 90 top
R239  4K7R2J-2-GP  [R402H16]  157.55 83.55 90 bottom
R240  10KR2F-2-GP  [R402H16]  99.13 94.98 90 bottom
R241  80D6R2F-L-GP  [R402H16]  77.18 91.3 270 top
R243  10KR2F-2-GP  [R402H16]  99.13 94.98 90 top
R244  162R2F-GP  [R402H16]  77.54 88.84 0 top
R245  80D6R2F-L-GP  [R402H16]  77.18 90.28 270 top
R246  0R2J-2-GP  [R402H16]  139.95 70.39 180 bottom
R247  0R2J-2-GP  [R402H16]  142 72.6 270 bottom
R249  10KR2J-3-GP  [R402H16]  114.24 67.55 180 top
R250  17K8R2F-GP  [R402H16]  92.27 55.74 270 top
R251  1KR2J-1-GP  [R402H16]  111.83 61.58 180 bottom
R252  10KR2F-2-GP  [R402H16]  94.43 53.45 90 top
R253  2K2R2J-2-GP  [R402H16]  99.64 62.85 90 top
R254  2K2R2J-2-GP  [R402H16]  124.02 48.5 270 top
R255  6K49R2F-1-GP  [R402H16]  99.92 52.18 270 top
R256  -  [0R0402-PAD]  110.69 61.58 0 bottom
R257  10KR2J-3-GP  [R402H16]  113.1 48.4 0 bottom
R258  4K99R2F-L-GP  [R402H16]  90.8 88.45 180 top
R259  10KR2F-2-GP  [R402H16]  97.05 52.97 180 top
R260  10KR2F-2-GP  [R402H16]  91.26 52.31 90 top
R262  10KR2J-3-GP  [R402H16]  121.48 47.1 270 top
R263  10KR2J-3-GP  [R402H16]  117.54 60.26 180 bottom
R264  10KR2J-3-GP  [R402H16]  115.26 67.55 180 top
R265  10KR2J-3-GP  [R402H16]  95.95 63.74 270 top
R266  5K1R2F-2-GP  [R402H16]  101.29 51.8 90 bottom
R267  10KR2J-3-GP  [R402H16]  114.12 48.4 180 bottom
R268  10KR2J-3-GP  [R402H16]  115.28 48.39 180 bottom
R269  10KR2J-3-GP  [R402H16]  116.53 48.4 180 bottom
R270  10KR2J-3-GP  [R402H16]  111.19 68.95 180 top
R272  10KR2F-2-GP  [R402H16]  103.83 52.31 0 bottom
R277  10KR2J-3-GP  [R402H16]  99.64 62.72 270 bottom
R279  10KR2J-3-GP  [R402H16]  108.27 71.36 90 top
R280  10KR2F-2-GP  [R402H16]  108.27 70.34 270 top
R283  10KR2J-3-GP  [R402H16]  104.59 68.69 180 top
R284  1KR2J-1-GP  [R402H16]  124.02 49.77 90 top
R285  1KR2J-1-GP  [R402H16]  122.69 58.63 90 top
R286  1KR2J-1-GP  [R402H16]  99.92 53.2 270 top
R287  4K7R2F-GP  [R402H16]  125.35 60.69 270 top
R288  100KR2J-1-GP  [R402H16]  119.55 58.1 270 bottom
R290  10KR2F-2-GP  [R402H16]  123.39 55.23 270 bottom
R291  -  [0R0402-PAD]  99.38 56.5 270 top
R292  0R0402-PAD-2-GP  [0R0402-PAD-1]  122.9 56.77 180 bottom
R293  20KR2J-L2-GP  [R402H16]  119.88 55.76 180 bottom
R294  33R2J-2-GP  [R402H16]  115.84 58.25 90 bottom
R295  0R0402-PAD-2-GP  [0R0402-PAD-1]  99.38 57.52 270 top
R296  10KR2J-3-GP  [R402H16]  119.83 60.57 180 bottom
R297  0R0402-PAD-2-GP  [0R0402-PAD-1]  99.38 58.53 270 top
R298  33R2J-2-GP  [R402H16]  122.62 63.23 180 top
R299  0R0402-PAD-2-GP  [0R0402-PAD-1]  123.77 63.23 180 top
R300  100R2F-L1-GP-U  [R402H14]  99.64 65.01 270 top
R301  0R0402-PAD-2-GP  [0R0402-PAD-1]  119.7 63.36 0 bottom
R302  0R0402-PAD-2-GP  [0R0402-PAD-1]  99.64 66.03 270 top
R303  1KR2J-1-GP  [R402H16]  99.64 68.06 270 top
R304  0R3J-0-U-GP  [R603H22]  125.11 55.87 180 top
R305  -  [0R0603-PAD]  92.93 65.39 90 top
R306  0R0402-PAD-2-GP  [0R0402-PAD-1]  98.88 69.96 270 top
R307  0R0402-PAD-2-GP  [0R0402-PAD-1]  98.88 70.98 270 top
R308  10KR2F-2-GP  [R402H16]  94.05 70.85 270 top
R309  10KR2F-2-GP  [R402H16]  93.16 69.2 270 top
R310  10KR2F-2-GP  [R402H16]  92.68 67.6 270 top
R311  10KR2F-2-GP  [R402H16]  102.76 64.5 180 bottom
R312  10KR2F-2-GP  [R402H16]  102.18 67.17 270 bottom
R313  10KR2F-2-GP  [R402H16]  102.18 68.31 270 bottom
R314  10KR2J-3-GP  [R402H16]  123.13 57.52 90 top
R316  10KR2J-3-GP  [R402H16]  119.53 50.35 270 bottom
R317  10KR2J-3-GP  [R402H16]  92.68 66.58 90 top
R318  4K7R2J-2-GP  [R402H16]  95.29 65.44 90 top
R319  100KR2J-1-GP  [R402H16]  114.32 69.99 270 top
R320  10KR2F-2-GP  [R402H16]  106.75 70.73 0 top
R321  10KR2F-2-GP  [R402H16]  106.62 68.69 0 top
R323  330R3J-L-GP  [R603H22]  113.35 59.17 0 bottom
R324  10KR2J-3-GP  [R402H16]  118.69 60.26 0 bottom
R327  2KR2J-1-GP  [R402H16]  117.24 63.59 0 bottom
R332  0R0402-PAD-2-GP  [0R0402-PAD-1]  100.02 59.8 90 top
R333  0R2J-2-GP  [R402H16]  99.64 60.82 90 top
R334  0R0402-PAD-2-GP  [0R0402-PAD-1]  100.02 61.2 180 bottom
R335  1KR2J-1-GP  [R402H16]  92.14 63.74 90 top
R336  0R0402-PAD-2-GP  [0R0402-PAD-1]  92.14 62.72 270 top
R337  1KR2J-1-GP  [R402H16]  94.81 58.03 90 top
R338  1KR2J-1-GP  [R402H16]  91.64 59.17 0 top
R339  20KR2J-L2-GP  [R402H16]  92.14 60.69 90 top
R340  1KR2J-1-GP  [R402H16]  95.95 62.72 270 top
R341  -  [0R0402-PAD]  152.47 87.62 270 bottom
R342  0R2J-2-GP  [R402H16]  153.99 88.25 180 bottom
R343  1KR2J-1-GP  [R402H16]  169.21 84.06 180 bottom
R345  1KR2J-1-GP  [R402H16]  168.22 90.03 0 top
R347  15R2J-GP  [R402H16]  166.57 82.97 180 bottom
R348  15R2J-GP  [R402H16]  169.36 90.03 180 top
R351  15R2J-GP  [R402H16]  168.19 83.17 0 bottom
R352  15R2J-GP  [R402H16]  170.5 90.03 180 top
R355  15R2J-GP  [R402H16]  171.65 90.03 180 top
R357  1KR2J-1-GP  [R402H16]  125.55 105.4 0 top
R359  2K2R2J-2-GP  [R402H16]  8.96 169.66 0 bottom
R360  100R2F-L1-GP-U  [R402H14]  8.96 171.69 180 bottom
R361  4K7R2J-2-GP  [R402H16]  8.45 174.99 270 bottom
R362  8K2R2F-1-GP  [R402H16]  6.93 174.23 180 bottom
R363  0R0402-PAD-2-GP  [0R0402-PAD-1]  5.78 172.71 180 bottom
R364  20KR2J-L2-GP  [R402H16]  8.45 173.85 90 bottom
R365  10KR2F-2-GP  [R402H16]  185.74 59.93 270 top
R366  5K1R2F-2-GP  [R402H16]  185.74 61.07 270 top
R367  20KR2F-L-GP  [R402H16]  184.85 63.74 90 top
R368  -  [0R0603-PAD]  175.33 52.21 0 top
R369  68R2F-GP  [R402H16]  172.41 53.88 270 top
R370  0R0402-PAD-2-GP  [0R0402-PAD-1]  172.5 66.61 270 top
R371  47KR2F-GP  [R402H16]  172.51 67.84 270 top
R372  47KR2F-GP  [R402H16]  172.51 65.56 90 top
R373  10KR2J-3-GP  [R402H16]  172.56 62.79 270 top
R374  -  [0R0402-PAD]  169.36 57.54 180 top
R375  0R2J-2-GP  [R402H16]  170.83 56.63 180 top
R376  33R2J-2-GP  [R402H16]  170.88 55.15 90 top
R377  0R2J-2-GP  [R402H16]  172.41 60.81 0 top
R378  33KR2J-3-GP  [R402H16]  170.48 63.92 270 top
R379  0R0402-PAD-2-GP  [0R0402-PAD-1]  170.92 46.77 90 top
R380  10R3J-3-GP  [R603H22]  165.8 33.26 180 top
R381  0R0402-PAD-2-GP  [0R0402-PAD-1]  177.2 33.34 180 top
R382  -  [0R0603-PAD]  179.27 40.63 0 top
R383  -  [0R0603-PAD]  183.2 43.29 90 top
R384  -  [0R0603-PAD]  174.85 42.66 270 top
R385  10K5R3F-GP  [R603H22]  172.41 43.93 270 top
R386  10K5R3F-GP  [R603H22]  183.2 44.56 90 top
R387  -  [0R0603-PAD]  172.81 41.93 180 top
R388  100KR2J-1-GP  [R402H16]  181.68 34.78 90 top
R389  20KR2J-L2-GP  [R402H16]  178.24 33.25 0 top
R390  20KR2J-L2-GP  [R402H16]  184.19 34.8 90 top
R391  4K7R2J-2-GP  [R402H16]  183.13 36.33 180 top
R392  10KR2J-3-GP  [R402H16]  184.35 40.25 0 bottom
R393  1KR2J-1-GP  [R402H16]  184.17 36.31 0 top
R394  10KR2J-3-GP  [R402H16]  185.22 36.32 180 top
R396  100KR2J-1-GP  [R402H16]  173.84 40.04 270 top
R397  2K2R2J-2-GP  [R402H16]  177.86 37.35 270 top
R398  10KR2F-2-GP  [R402H16]  176.76 38.9 180 top
R399  5K6R2F-2-GP  [R402H16]  172.93 38.98 270 top
R400  3D3R3F-GP  [R603H22]  164.15 23.48 90 bottom
R401  3D3R3F-GP  [R603H22]  167.07 23.48 270 bottom
R402  3D3R3F-GP  [R603H22]  175.33 23.48 270 bottom
R403  3D3R3F-GP  [R603H22]  172.41 23.51 90 bottom
R404  2K2R2J-2-GP  [R402H16]  189.3 76.95 0 top
R405  2K2R2J-2-GP  [R402H16]  189.3 74.15 180 top
R406  10R2F-L-GP  [R402H14]  184.35 73.27 0 top
R407  100KR2F-L1-GP  [R402H16]  176.98 77.08 0 top
R408  1MR3F-GP  [R603H22]  178.25 77.33 180 top
R409  10R2F-L-GP  [R402H14]  187.06 72.63 270 top
R410  1KR2J-1-GP  [R402H16]  185.54 71.28 180 top
R411  1KR2J-1-GP  [R402H16]  187.99 71.18 180 top
R412  10KR2J-3-GP  [R402H16]  189.3 78.85 180 top
R413  10KR2J-3-GP  [R402H16]  189.68 70.98 0 top
R414  2K2R2J-2-GP  [R402H16]  184.4 71.28 180 top
R415  2K2R2J-2-GP  [R402H16]  185.49 73.27 0 top
R416  1KR2J-1-GP  [R402H16]  174.57 71.74 180 top
R417  0R0402-PAD-2-GP  [0R0402-PAD-1]  188.28 80.76 0 top
R418  0R0402-PAD-2-GP  [0R0402-PAD-1]  189.43 80.76 0 top
R419  0R3J-0-U-GP  [R603H22]  190.57 80.76 0 top
R420  0R0402-PAD-2-GP  [0R0402-PAD-1]  182.06 78.73 90 top
R421  47R2J-2-GP  [R402H16]  105.1 31.36 180 top
R422  47R2J-2-GP  [R402H16]  103.96 31.36 180 top
R423  SCD1U16V2KX-3DLGP  [C402H22]  90.87 34.02 90 top
R424  SCD1U16V2KX-3DLGP  [C402H22]  102.56 30.21 180 top
R425  0R2J-2-GP  [R402H16]  69.56 35.86 180 top
R426  10KR2J-3-GP  [R402H16]  60.78 14.08 180 top
R435  8K2R2J-3-GP  [R402H16]  53.41 47.08 270 top
R436  1KR2J-1-GP  [R402H16]  52.77 39.61 90 top
R438  2KR2F-3-GP  [R402H16]  54.55 48.25 270 top
R439  15KR2F-GP  [R402H16]  52.77 40.75 270 top
R440  1KR2J-1-GP  [R402H16]  51.38 46.47 270 top
R442  1MR3F-GP  [R603H22]  54.81 32.88 180 top
R451  0R2J-2-GP  [R402H16]  175.46 104.13 270 top
R452  0R2J-2-GP  [R402H16]  183.97 106.54 0 bottom
R453  0R2J-2-GP  [R402H16]  175.46 105.52 270 top
R454  0R2J-2-GP  [R402H16]  175.46 106.92 270 top
R455  10KR2J-3-GP  [R402H16]  174.95 102.35 0 top
R456  0R2J-2-GP  [R402H16]  175.33 102.09 90 bottom
R457  33KR2F-GP  [R402H16]  185.24 105.02 270 bottom
R458  0R0402-PAD-2-GP  [0R0402-PAD-1]  186.51 138.67 180 bottom
R462  1KR2J-1-GP  [R402H16]  110.56 39.74 90 top
R463  10KR2J-3-GP  [R402H16]  127.32 24.88 270 top
R464  15KR2F-GP  [R402H16]  125.8 27.29 90 top
R465  0R2J-2-GP  [R402H16]  115 26.91 0 top
R466  1KR2J-1-GP  [R402H16]  180.54 89.39 180 top
R467  10KR2J-3-GP  [R402H16]  134.18 24.75 90 top
R468  0R2J-2-GP  [R402H16]  113.73 26.91 0 top
R469  15KR2F-GP  [R402H16]  135.2 26.78 90 top
R470  10KR2J-3-GP  [R402H16]  175.46 97.52 0 top
R471  1KR2J-1-GP  [R402H16]  179.39 89.39 180 top
R472  15KR2F-GP  [R402H16]  173.93 97.14 270 top
R473  0R3J-0-U-GP  [R603H22]  176.22 200.9 270 top
R474  0R3J-0-U-GP  [R603H22]  176.22 195.06 270 top
R475  10KR2J-3-GP  [R402H16]  170.12 205.35 270 top
R484  100KR2J-1-GP  [R402H16]  78.94 30.34 0 bottom
R485  10KR3J-L1-GP  [R603H22]  79.83 38.67 90 bottom
R486  56KR3F-GP  [R603H22]  85.92 28.05 0 top
R492  1K5R2J-3-GP  [R402H16]  53.66 31.1 0 top
R495  33R2J-2-GP  [R402H16]  49.29 28.43 180 bottom
R499  10KR2J-3-GP  [R402H16]  52.01 25.89 90 bottom
R501  100KR2J-1-GP  [R402H16]  52.01 24.75 90 bottom
R503  15KR2F-GP  [R402H16]  50.49 25.01 0 bottom
R505  0R2J-2-GP  [R402H16]  76.52 64.76 90 top
R506  0R2J-2-GP  [R402H16]  76.52 67.8 90 top
R507  470KR2F-GP  [R402H16]  80.08 59.63 0 top
R508  10KR2J-3-GP  [R402H16]  82.92 54.85 180 top
R509  100KR2J-1-GP  [R402H16]  80.18 61.89 180 top
R510  1MR2J-1-GP  [R402H16]  81.76 54.85 180 top
R511  4K7R2J-2-GP  [R402H16]  87.85 56.09 270 bottom
R512  100KR2J-1-GP  [R402H16]  78.94 59.65 180 top
R513  0R2J-2-GP  [R402H16]  77.41 47.61 90 bottom
R515  1K5R3-GP  [R603H22]  65.75 52.26 180 bottom
R517  10KR2J-3-GP  [R402H16]  27.37 51.17 90 top
R522  -  [0R0402-PAD]  16.83 21.96 0 top
R523  10KR2J-3-GP  [R402H16]  24.2 46.47 270 bottom
R524  10KR2J-3-GP  [R402H16]  17.09 43.17 0 bottom
R530  10KR2J-3-GP  [R402H16]  17.98 21.96 180 top
R531  10KR2J-3-GP  [R402H16]  20.77 46.85 90 bottom
R533  10KR2J-3-GP  [R402H16]  19.12 47.1 0 bottom
R535  4K7R2J-2-GP  [R402H16]  19.5 41.77 270 bottom
R584  100KR2J-1-GP  [R402H16]  97.73 116.95 90 top
R586  0R5J-5-GP  [R805H24]  96.59 122.92 90 top
R587  243R2F-2-GP  [R402H16]  56.71 96.76 270 top
R591  10KR2J-3-GP  [R402H16]  89.16 119.77 90 bottom
R596  10KR2J-3-GP  [R402H16]  94.05 84.82 90 top
R597  10KR2J-3-GP  [R402H16]  94.05 85.97 270 top
R598  33KR2J-3-GP  [R402H16]  93.59 83.32 0 top
R599  10KR2J-3-GP  [R402H16]  60.9 91.98 180 top
R602  2K2R2J-2-GP  [R402H16]  97.61 88.51 180 top
R603  2K2R2J-2-GP  [R402H16]  94.81 85.58 0 bottom
R604  60D4R2F-GP  [R402H16]  76.19 107.67 270 bottom
R605  1KR2J-1-GP  [R402H16]  100.65 116.95 270 top
R606  0R0402-PAD-2-GP  [0R0402-PAD-1]  90.24 108.32 90 bottom
R607  10KR2F-2-GP  [R402H16]  99.13 92.95 270 top
R608  60D4R2F-GP  [R402H16]  76.65 106.18 0 bottom
R609  33R2J-2-GP  [R402H16]  97.22 93.08 90 top
R610  40K2R2F-GP  [R402H16]  88.87 104.61 0 bottom
R611  40D2R2F  [R402H16]  77.34 102.51 180 bottom
R612  4K99R2F-L-GP  [R402H16]  91.31 85.74 90 top
R613  4K99R2F-L-GP  [R402H16]  90.87 84.26 0 top
R615  100KR2J-1-GP  [R402H16]  84.71 103.5 180 bottom
R616  100KR2J-1-GP  [R402H16]  89.9 103.62 0 bottom
R619  100KR2J-1-GP  [R402H16]  90.04 100.89 180 bottom
R620  243R2F-2-GP  [R402H16]  77.03 91.05 270 bottom
R621  10KR2F-2-GP  [R402H16]  85.25 100.11 90 bottom
R622  100KR2J-1-GP  [R402H16]  89.01 101.69 180 bottom
R625  33R2J-2-GP  [R402H16]  101.15 88.04 270 top
R626  33R2J-2-GP  [R402H16]  97.99 90.92 270 top
R628  2K2R2J-2-GP  [R402H16]  95.45 98.92 90 bottom
R629  10KR2F-2-GP  [R402H16]  87.09 100.51 0 bottom
R630  100KR2J-1-GP  [R402H16]  92.14 105.9 90 bottom
R631  100KR2J-1-GP  [R402H16]  92.27 102.35 0 bottom
R632  0R0402-PAD-2-GP  [0R0402-PAD-1]  91.64 104.89 270 bottom
R633  10KR2F-2-GP  [R402H16]  100.53 90.92 0 top
R692  -  [0R0805-PAD]  27.97 113.96 180 top
R693  -  [0R0805-PAD]  25.92 113.96 180 top
R701  0R2J-2-GP  [R402H16]  137.5 245.74 270 top
R702  0R2J-2-GP  [R402H16]  137.5 244.73 270 top
R704  0R2J-2-GP  [R402H16]  137.5 243.71 270 top
R706  0R2J-2-GP  [R402H16]  137.5 242.69 270 top
R707  0R2J-2-GP  [R402H16]  137.5 241.68 270 top
R708  0R0402-PAD-2-GP  [0R0402-PAD-1]  118.45 244.22 270 top
R709  0R0402-PAD-2-GP  [0R0402-PAD-1]  118.45 243.2 270 top
R710  0R2J-2-GP  [R402H16]  118.45 242.19 270 top
R711  0R0402-PAD-2-GP  [0R0402-PAD-1]  118.45 240.15 270 top
R712  0R0402-PAD-2-GP  [0R0402-PAD-1]  118.45 239.14 270 top
R713  0R2J-2-GP  [R402H16]  138.68 239.03 270 top
R714  0R0402-PAD-2-GP  [0R0402-PAD-1]  118.45 238.12 270 top
R715  0R0402-PAD-2-GP  [0R0402-PAD-1]  118.45 241.17 270 top
R716  0R2J-2-GP  [R402H16]  138.69 238 270 top
R717  0R0402-PAD-2-GP  [0R0402-PAD-1]  118.45 237.11 270 top
R718  0R2J-2-GP  [R402H16]  138.69 236.98 270 top
R719  0R0402-PAD-2-GP  [0R0402-PAD-1]  118.45 236.09 270 top
R720  0R0402-PAD-2-GP  [0R0402-PAD-1]  118.45 235.07 270 top
R721  0R2J-2-GP  [R402H16]  120.49 227.47 270 top
R722  0R0402-PAD-2-GP  [0R0402-PAD-1]  120.49 228.48 270 top
R723  0R5J-5-GP  [R805H24]  144.59 228.06 180 bottom
R725  10KR2J-3-GP  [R402H16]  136.34 249.67 90 top
R727  8K2R2J-3-GP  [R402H16]  145.36 236.71 180 top
R728  100KR2J-1-GP  [R402H16]  132.15 254.62 0 top
R729  0R2J-2-GP  [R402H16]  150.56 236.97 180 top
R730  39K2R2F-L-GP  [R402H16]  144.21 236.84 0 top
R731  10KR2J-3-GP  [R402H16]  125.04 251.7 270 top
R732  0R0402-PAD-2-GP  [0R0402-PAD-1]  151.83 236.97 180 top
R734  10KR2J-3-GP  [R402H16]  150.69 242.43 90 top
R738  10KR2J-3-GP  [R402H16]  17.98 137.4 0 top
R740  1KR2J-1-GP  [R402H16]  21.66 17.89 0 top
R741  10KR2J-3-GP  [R402H16]  52.39 6.46 0 top
R742  33R2J-2-GP  [R402H16]  24.45 18.02 180 top
R743  -  [0R0402-PAD]  20.52 15.61 180 top
R744  3KR2J-2-GP  [R402H16]  50.62 9.36 90 top
R745  10KR2F-2-GP  [R402H16]  24.45 15.99 0 top
R746  33R2J-2-GP  [R402H16]  23.44 15.99 180 top
R747  10KR2J-3-GP  [R402H16]  50.95 12.46 270 top
R748  4K7R2J-2-GP  [R402H16]  21.66 19.93 0 top
R749  3KR2J-2-GP  [R402H16]  50.95 11.44 270 top
R750  33R2J-2-GP  [R402H16]  24.45 20.05 180 top
R751  75R3F-GP  [R603H22]  38.17 12.69 180 top
R752  75R3F-GP  [R603H22]  35.55 10.68 270 top
R753  4K7R2J-2-GP  [R402H16]  21.66 21.96 180 top
R754  33R2J-2-GP  [R402H16]  24.45 21.96 180 top
R755  4K7R2J-2-GP  [R402H16]  43.5 5.45 0 top
R756  75R3F-GP  [R603H22]  38.93 10.65 90 top
R757  75R3F-GP  [R603H22]  39.69 12.69 180 top
R758  0R2J-2-GP  [R402H16]  39.19 7.86 0 top
R759  0R2J-2-GP  [R402H16]  44.65 11.54 0 top
R760  4K7R2J-2-GP  [R402H16]  43.63 9.26 180 top
R762  -  [0R0402-PAD]  44.65 9.13 90 bottom
R763  4K7R2J-2-GP  [R402H16]  138.12 49.39 90 top
R764  10KR2J-3-GP  [R402H16]  135.83 49.52 90 top
R876  10KR2J-3-GP  [R402H16]  162.12 72.12 90 top
R886  -  [0R0603-PAD]  155.01 72.05 90 bottom
R889  -  [0R0603-PAD]  144.29 77.48 270 bottom
R890  -  [0R0603-PAD]  132.15 62.85 0 top
R891  -  [0R0603-PAD]  130.12 94.22 270 top
R892  -  [0R0603-PAD]  137.36 99.17 0 bottom
R894  45K3R2F-L-GP  [R402H16]  127.2 97.9 90 top
R925  470R2F-GP  [R402H16]  169.49 187.57 180 bottom
R1129  8K2R2J-3-GP  [R402H16]  95.45 109.97 0 top
R1163  1KR2F-3-GP  [R402H16]  25.06 52.67 90 top
R1194  10KR2J-3-GP  [R402H16]  60.27 12.56 270 top
R1195  39K2R2F-L-GP  [R402H16]  95.19 115.56 180 top
R1203  0R0402-PAD-2-GP  [0R0402-PAD-1]  176.08 27.71 0 top
R1212  0R0402-PAD-2-GP  [0R0402-PAD-1]  100.35 115.23 0 top
R1592  36R3F-GP  [R603H22]  140.66 49.39 270 top
R1593  4K7R2F-GP  [R402H16]  151.58 45.45 90 top
R1594  4K7R2F-GP  [R402H16]  159.71 36.94 270 bottom
R1596  4K7R2F-GP  [R402H16]  167.2 45.45 90 top
R1598  4K7R2F-GP  [R402H16]  151.58 47.74 90 top
R1659  10KR2J-3-GP  [R402H16]  136.72 91.81 90 bottom
R1660  10KR2J-3-GP  [R402H16]  136.72 90.66 270 bottom
R1661  10KR2J-3-GP  [R402H16]  135.96 97.01 90 top
R1662  10KR2J-3-GP  [R402H16]  130.5 98.92 90 top
R1663  10KR2J-3-GP  [R402H16]  135.96 95.87 270 top
R1683  -  [0R0402-PAD]  41.47 153.4 180 top
R1684  10KR2J-3-GP  [R402H16]  138.37 92.32 180 bottom
R1685  10KR2J-3-GP  [R402H16]  138.25 90.41 180 bottom
R1687  10KR2J-3-GP  [R402H16]  133.17 100.57 90 top
R1688  10KR2J-3-GP  [R402H16]  133.17 99.55 90 top
R1730  -  [0R0603-PAD]  160.72 87.87 270 bottom
R1732  -  [0R0603-PAD]  154.5 61 0 top
R1733  10KR2J-3-GP  [R402H16]  32.45 11.54 0 top
R1734  10KR2F-2-GP  [R402H16]  111.07 243.32 270 top
R1735  100KR2J-1-GP  [R402H16]  111.32 238.24 270 top
R1736  -  [0R0402-PAD]  169.23 211.19 180 bottom
R1748  -  [0R0603-PAD]  32.86 127.6 270 top
R1749  -  [0R0603-PAD]  32.86 126.27 270 top
R1762  1KR2F-3-GP  [R402H16]  30.3 125.21 90 top
R1764  0R0402-PAD-2-GP  [0R0402-PAD-1]  42.49 122.29 90 top
R1766  1KR2F-3-GP  [R402H16]  41.47 134.48 90 top
R1769  150R2F-1-GP  [R402H16]  37.03 156.58 90 top
R1770  0R0402-PAD-2-GP  [0R0402-PAD-1]  32.66 123.53 180 top
R1771  1KR2J-1-GP  [R402H16]  33.7 123.53 180 top
R1773  0R0402-PAD-2-GP  [0R0402-PAD-1]  45.79 135.08 270 top
R1774  0R0402-PAD-2-GP  [0R0402-PAD-1]  45.79 134.06 270 top
R1775  1KR2F-3-GP  [R402H16]  46.42 128.38 270 top
R1776  2K2R2J-2-GP  [R402H16]  32.96 125.08 90 top
R1777  1KR2F-3-GP  [R402H16]  46.42 126.1 270 top
R1778  1KR2F-3-GP  [R402H16]  46.42 127.24 270 top
R1779  1KR2F-3-GP  [R402H16]  48.33 130.67 270 top
R1780  0R2J-2-GP  [R402H16]  32.96 119.49 270 top
R1782  0R2J-2-GP  [R402H16]  45.79 136.13 270 top
R1783  0R0402-PAD-2-GP  [0R0402-PAD-1]  30.3 126.35 270 top
R1784  0R0402-PAD-2-GP  [0R0402-PAD-1]  164.61 75.96 0 top
R1785  0R0402-PAD-2-GP  [0R0402-PAD-1]  158.95 69.86 270 bottom
R1786  0R0402-PAD-2-GP  [0R0402-PAD-1]  157.37 73.54 90 top
R1787  0R0402-PAD-2-GP  [0R0402-PAD-1]  159.07 55.36 90 top
R1789  51R2J-2-GP  [R402H16]  32.96 120.64 270 top
R1791  0R0402-PAD-2-GP  [0R0402-PAD-1]  48.33 129.53 270 top
R1792  0R0402-PAD-2-GP  [0R0402-PAD-1]  42.49 123.43 90 top
R1793  1KR2F-3-GP  [R402H16]  42.49 124.57 90 top
R1794  4K7R2J-2-GP  [R402H16]  149.93 92.32 0 bottom
R1797  20KR2J-L2-GP  [R402H16]  160.34 80.89 90 bottom
R1798  4K7R2J-2-GP  [R402H16]  160.34 81.9 270 bottom
R1799  1KR2J-1-GP  [R402H16]  160.22 83.43 270 bottom
R1800  1KR2J-1-GP  [R402H16]  160.22 84.57 270 bottom
R1801  10KR2J-3-GP  [R402H16]  174.57 207 0 bottom
R1804  560R2J-3-GP  [R402H16]  151.71 52.18 90 top
R1807  22R2J-2-GP  [R402H16]  157.36 74.78 90 top
R1811  30R2J-1-GP  [R402H16]  142.82 61.28 0 top
R1812  10KR2J-3-GP  [R402H16]  142.79 97.38 180 top
R1815  10KR2J-3-GP  [R402H16]  139.39 92.7 0 bottom
R1816  10KR2J-3-GP  [R402H16]  138.88 96.38 270 top
R1817  10KR2J-3-GP  [R402H16]  138.88 97.52 270 top
R1820  10KR2J-3-GP  [R402H16]  138.03 94.91 180 top
R1821  100R2F-L1-GP-U  [R402H14]  37.38 230.11 90 top
R1822  -  [0R0603-PAD]  59.45 143.12 90 top
R1823  0R2J-2-GP  [R402H16]  57.98 141.85 270 top
R1824  0R0402-PAD-2-GP  [0R0402-PAD-1]  57.98 140.7 270 top
R1826  10KR2J-3-GP  [R402H16]  123.07 60.69 90 top
R1828  1KR2J-1-GP  [R402H16]  157.55 84.7 270 bottom
R1829  4K7R2J-2-GP  [R402H16]  157.68 81.9 90 bottom
R1830  1KR2J-1-GP  [R402H16]  169.64 82.56 270 bottom
R1832  0R0402-PAD-2-GP  [0R0402-PAD-1]  32.96 118.35 90 top
R1833  20KR2J-L2-GP  [R402H16]  159.58 88.51 180 top
R1834  4K7R2J-2-GP  [R402H16]  160.72 88.51 0 top
R1835  1MR2J-1-GP  [R402H16]  157.85 70.93 90 bottom
R1836  1KR2J-1-GP  [R402H16]  124.15 50.91 90 bottom
R1837  1KR2J-1-GP  [R402H16]  149.68 98.92 270 top
R1838  1KR2J-1-GP  [R402H16]  149.7 99.02 90 bottom
R1839  150KR2F-L-GP  [R402H16]  147.02 97.65 90 bottom
R1840  20KR2J-L2-GP  [R402H16]  147.01 96.63 90 bottom
R1841  51R2F-2-GP  [R402H16]  145.33 65.92 180 bottom
R1842  51R2F-2-GP  [R402H16]  148.91 58.41 0 top
R1922  10KR2J-3-GP  [R402H16]  162.12 78.22 270 top
R1923  10KR2J-3-GP  [R402H16]  130.5 100.06 90 top
R1946  4K7R2J-2-GP  [R402H16]  123.13 55.23 270 top
R1947  0R2J-2-GP  [R402H16]  151.71 122.8 270 top
R1948  -  [0R0402-PAD]  123.64 53.71 90 bottom
R1949  -  [0R0402-PAD]  124.02 52.06 270 top
R1950  0R2J-2-GP  [R402H16]  97.41 58.79 90 top
R1951  -  [0R0402-PAD]  97.41 57.64 270 top
R1952  1KR2J-1-GP  [R402H16]  173.93 204.46 270 bottom
R1953  10KR2F-2-GP  [R402H16]  160.22 208.77 180 bottom
R1954  10KR2J-3-GP  [R402H16]  166.19 206.36 0 bottom
R1955  1KR2J-1-GP  [R402H16]  173.04 206.49 270 bottom
R1956  10KR2J-3-GP  [R402H16]  162.76 209.66 180 bottom
R1957  0R0402-PAD-2-GP  [0R0402-PAD-1]  167.33 206.36 0 bottom
R1958  0R2J-2-GP  [R402H16]  161.36 208.77 180 bottom
R1961  10KR2J-3-GP  [R402H16]  19.88 162.04 270 top
R1963  100KR2J-1-GP  [R402H16]  20.14 156.2 270 top
R1964  10KR2J-3-GP  [R402H16]  17.85 160.97 90 top
R1966  0R2J-2-GP  [R402H16]  35.76 255.51 0 top
R1967  0R2J-2-GP  [R402H16]  17.85 162.11 90 top
R1968  0R2J-2-GP  [R402H16]  18.69 163.59 180 top
R1969  0R2J-2-GP  [R402H16]  33.34 253.99 90 top
R1970  10KR2J-3-GP  [R402H16]  30.42 257.03 180 bottom
R1971  0R2J-2-GP  [R402H16]  23.39 257.19 270 bottom
R1972  249R2F-GP  [R402H16]  21.53 254.75 270 top
R1973  -  [0R0402-PAD]  21.53 252.46 90 top
R1977  -  [0R0402-PAD]  26.61 253.86 0 top
R1979  0R2J-2-GP  [R402H16]  24.96 255.51 90 bottom
R1980  249R2F-GP  [R402H16]  21.53 253.61 270 top
R1981  30R2J-1-GP  [R402H16]  143.86 61.28 0 top
R1982  30R2J-1-GP  [R402H16]  154.5 83.43 270 bottom
R1983  22R2J-2-GP  [R402H16]  154.5 75.93 270 bottom
R1984  -  [0R0402-PAD]  127.83 47.61 270 top
R1985  0R6J-L-GP  [R1206H26]  36.44 173.93 0 top
R1986  0R6J-L-GP  [R1206H26]  38.65 173.93 0 top
R1988  100KR2J-1-GP  [R402H16]  41.98 150.74 270 top
R1989  47KR2J-2-GP  [R402H16]  42.36 149.21 0 top
R1990  100KR2J-1-GP  [R402H16]  41.98 151.88 90 top
R1991  100KR2J-1-GP  [R402H16]  43.38 149.21 0 top
R1992  10KR2J-3-GP  [R402H16]  41.09 149.21 180 top
R1993  1KR2J-1-GP  [R402H16]  94.81 56.37 180 top
R1994  47KR2J-2-GP  [R402H16]  151.2 70.98 270 bottom
R1996  560R2J-3-GP  [R402H16]  69.92 179.44 180 bottom
R2081  180R3F-GP  [R603H22]  140.91 47.61 270 top
R2082  4K99R2F-L-GP  [R402H16]  155.01 44.39 270 top
R2083  2K2R2J-2-GP  [R402H16]  166.44 42.53 270 top
R2084  2K2R2J-2-GP  [R402H16]  169.23 42.53 90 top
R2085  4K7R2F-GP  [R402H16]  155.01 45.45 90 top
R2086  4K7R2F-GP  [R402H16]  167.2 44.31 270 top
R2087  4K7R2F-GP  [R402H16]  151.58 48.88 90 top
R2088  4K7R2F-GP  [R402H16]  151.58 46.6 90 top
